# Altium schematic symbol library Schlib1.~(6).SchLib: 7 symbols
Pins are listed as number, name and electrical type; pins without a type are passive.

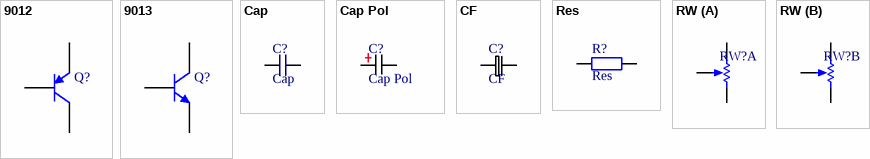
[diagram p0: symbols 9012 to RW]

## 9012
designator Q?  (value not drawn)
PNP General Purpose Amplifier
pins: 1 E, 2 B, 3 C

## 9013
designator Q?  (value not drawn)
NPN General Purpose Amplifier
pins: 1 E, 2 B, 3 C

## Cap
designator C?
pins: 1, 2

## Cap Pol
designator C?
pins: 1, 2

## CF
designator C?
pins: 1, 2

## Res
designator R?
Resistor; Value: 1K
pins: 1, 2

## RW
designator RW?  (value not drawn)
part A pins: 1 TOP, 2 TAP, 3 BOT
part B pins: 4 TOP, 5 TAP, 6 BOT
